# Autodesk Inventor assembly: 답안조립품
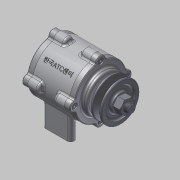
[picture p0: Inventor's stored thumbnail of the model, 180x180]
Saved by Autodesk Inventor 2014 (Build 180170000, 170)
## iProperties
Created: 2015-03
Part Number: 답안조립품
Document SubType Name: Assembly
Designer: MYHOME
Author: MYHOME
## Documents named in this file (11)
- C:\Documents and Settings\MYHOME\바탕 화면\450306V1019\답안조립품.iam
- C:\Documents and Settings\MYHOME\바탕 화면\450306V1019\본체.ipt
- C:\Documents and Settings\MYHOME\바탕 화면\450306V1019\커버.ipt
- C:\Documents and Settings\MYHOME\바탕 화면\450306V1019\커버2.ipt
- C:\Documents and Settings\MYHOME\바탕 화면\450306V1019\오일실.ipt
- C:\Documents and Settings\MYHOME\바탕 화면\450306V1019\M 4 x 12.ipt
- C:\Documents and Settings\MYHOME\바탕 화면\450306V1019\축.ipt
- C:\Documents and Settings\MYHOME\바탕 화면\450306V1019\베어링 6204.ipt
- C:\Documents and Settings\MYHOME\바탕 화면\450306V1019\키(4 x 4 x 12).ipt
- C:\Documents and Settings\MYHOME\바탕 화면\450306V1019\V벨트풀리.ipt
- C:\Documents and Settings\MYHOME\바탕 화면\450306V1019\너트 M12x1.25.ipt
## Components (14 placed, 6 different names)
1. KS B 2804 D D - 20 32 8:1
2. KS B 2023 6204 - 20 x 47 x 14:1 — 각도:1
3. KS B 2023 6204 - 20 x 47 x 14:2 — 각도:2
4. KS B 1311 (I) 4 x 4 x 12:1
5. 그루브 풀리1:1
6. KS B 1012 클래스 1 일반 - 미터 M12x1.25:1 — 각도:3
7. KS B 1003 - 미터 M 4 x 12:1
8. KS B 1003 - 미터 M 4 x 12:2
9. KS B 1003 - 미터 M 4 x 12:3
10. KS B 1003 - 미터 M 4 x 12:4
11. KS B 1003 - 미터 M 4 x 12:5
12. KS B 1003 - 미터 M 4 x 12:6
13. KS B 1003 - 미터 M 4 x 12:7
14. KS B 1003 - 미터 M 4 x 12:8
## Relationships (3: Angle 3)
- 각도:1 [Angle]: KS B 2023 6204 - 20 x 47 x 14:1
- 각도:2 [Angle]: KS B 2023 6204 - 20 x 47 x 14:2
- 각도:3 [Angle]: KS B 1012 클래스 1 일반 - 미터 M12x1.25:1
